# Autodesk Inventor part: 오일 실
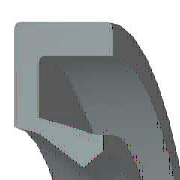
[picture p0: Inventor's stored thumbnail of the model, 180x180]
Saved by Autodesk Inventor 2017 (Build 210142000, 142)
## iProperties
IsCustomPart: 1
Created: 2012-02
Part Number: 오일 실
Material: 고무
Description: 오일 실 - 스프링 장착, 비스프링, 고무 덮개 G
Document SubType Name: Modeling
Standard: JIS B 2402
Designer: mduedu
Standards Organization: JIS
Language: ko-KR
Size Designation: 20 32 5 A
Categories: <MemberInstance><Categories><Category DisplayName="샤프트 부품" InternalName="7f7aeb1f-a693-4053-b835-cee3144e0d98" Mnemonic="SHFT"><Category DisplayName="실링" Intern
Density: 0.93 g/cm^3
Appearance: 고무 - 검은색 - 버전 1.1
Author: mduedu
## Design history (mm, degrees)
body "Solid1"
revolve "회전1" stored, may be unused: angle "d29" = 360 deg
chamfer "모따기1" distance "d30" = 0.25 (= 0.05 x b); stored, may be unused: second distance "d31" = 0.5 (= 0.1 x b), angle "d39" = 45 deg
chamfer "모따기2" distance "d32" = 0.5 (= 0.1 x b); stored, may be unused: second distance "d33" = 0.25 (= 0.05 x b), angle "d40" = 45 deg
fillet "모깎기1" dims "d34" = 0.25 (= 0.05 x b)
sketch "스케치2"
  geometry: L1 (10.997, -3.438)-(11.297, -5); L2 (10.597, -3.282)-(10.997, -3.438); L3 (10, -1.72)-(10.597, -3.282); L4 (11.091, -1.22)-(10, -1.72); L5 (12.133, -3.75)-(11.091, -1.22); L6 (13.333, -3.75)-(12.133, -3.75); L7 (14.667, -1.25)-(13.333, -3.75); L8 (14.667, 0)-(14.667, -1.25); L9 (16, 0)-(14.667, 0); L10 (16, -5)-(16, 0); L11 (11.297, -5)-(16, -5); L12 (0, -9.6)-(0, 1.6) reference; L13 (28, 0)-(14, 0) reference
  constraints: 22 end point, 3 horizontal, 2 vertical
  dimensions: "d2" = 5 distance of L10.start L9.start (= b); "d4" = 1.25 vertical distance of L5.start L1.end (= 0.25 x b); "d6" = 1.33333 distance of L9.start L8.start (= 0.111111 x dd - 0.111111 x Diam); "d8" = 1.25 distance of L8.start L7.start (= 0.25 x b); "d10" = 1.33333 horizontal distance of L7.start L6.start (= 0.111111 x dd - 0.111111 x Diam); "d12" = 1.21951 vertical distance of L9.start L4.start (= 0.243902 x b); "d14" = 1.09091 horizontal distance of L4.start L3.start (= 0.0909091 x dd - 0.0909091 x Diam); "d16" = 0.5 vertical distance of L4.start L3.start (= 0.1 x b); "d18" = 1.2 distance of L6.start L5.start (= 0.1 x dd - 0.1 x Diam); "d20" = 1.5625 vertical distance of L3.start L2.start (= 0.3125 x b); "d22" = 0.59701 horizontal distance of L3.start L2.start (= 0.0497512 x dd - 0.0497512 x Diam); "d24" = 0.3 horizontal distance of L1.start L1.end (= 0.025 x dd - 0.025 x Diam); "d26" = 1.5625 vertical distance of L1.start L1.end (= 0.3125 x b); "d28" = 0.4 horizontal distance of L2.start L1.start (= 0.0333333 x dd - 0.0333333 x Diam); "d35" = 0 distance between parallel lines of L13 L9; "d36" = 16 distance between parallel lines of L12 L10 (= 0.5 x dd); "d37" = 10 distance from line of L12 L3.start (= 0.5 x Diam)
other parameters: "dd" = 32 [user parameter; used in 8 equation terms], "b" = 5 [user parameter; used in 12 equation terms], "d1" = 8 (derived), "d3" = 2 (derived), "d5" = 2.22222 (derived), "d7" = 2 (derived), "d9" = 2.22222 (derived), "d11" = 1.95122 (derived), "d13" = 1.81818 (derived), "d15" = 0.8 (derived), "d17" = 2 (derived), "d19" = 2.5 (derived), "d21" = 0.99502 (derived), "d23" = 0.5 (derived), "d25" = 2.5 (derived), "d27" = 0.66667 (derived), "d38" = 0
